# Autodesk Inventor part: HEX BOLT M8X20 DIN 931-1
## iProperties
Created: 2006-02
Part Number: HEX BOLT M8X20 DIN 931-1
Material: Steel, Mild
Description: Hex-Head Bolt
Document SubType Name: Modeling
Standard: DIN 931-1
Designer: Andy Moles
Standards Organization: DIN
Language: en-US
Size Designation: M8 x 35
Categories: <MemberInstance><Categories><Category DisplayName="Fasteners" InternalName="e4da775c-781d-43d5-af7c-5136215cf5a6" Mnemonic="FSTN"><Category DisplayName="Bolts"
Density: 1 g/cm^3
Author: Andy Moles
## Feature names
1. Body [Revolution]
2. Head [Extrusion]
3. Chamfer1 [Revolution]
4. Chamfer2
